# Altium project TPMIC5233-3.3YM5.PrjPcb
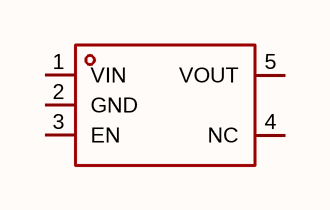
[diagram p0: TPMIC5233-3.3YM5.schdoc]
1 sheet, 1 parts. Net scope: global (net labels, ports and power ports of the same name join across sheets).

## Sheet TPMIC5233-3.3YM5.schdoc
size 127 x 101 mm

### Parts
U?  tpmic5233-3.3ym5  [SOT-23-5_L2.9-W1.6-P0.95-LS2.8-BL]  (value not drawn)

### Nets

Not connected (* = marked no-connect by the designer): U? 1(VIN) 2(GND) 3(EN) 4(NC) 5(VOUT)

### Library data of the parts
U? = tpmic5233-3.3ym5: 输出极性:正极;工作电压:36V;输出电压:3.3V;输出电流:200mA;电源纹波抑制比(PSRR):70dB@(100Hz);输出类型:固定;; Manufacturer: TECH PUBLIC(台舟); AddInBom: yes; ModelId: 018c57e721114987ae90467fe9f1d259; ModelTransform: 114.96,110.236,0,0,0,0,0,0,0; Output Configuration: 正极; Voltage - Supply: 36V; Output Voltage: 3.3V; Output Current: 200mA; Voltage Dropout: 750mV@(100mA); standby current: 2uA; Output Type: 固定; Number of Outputs: 1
